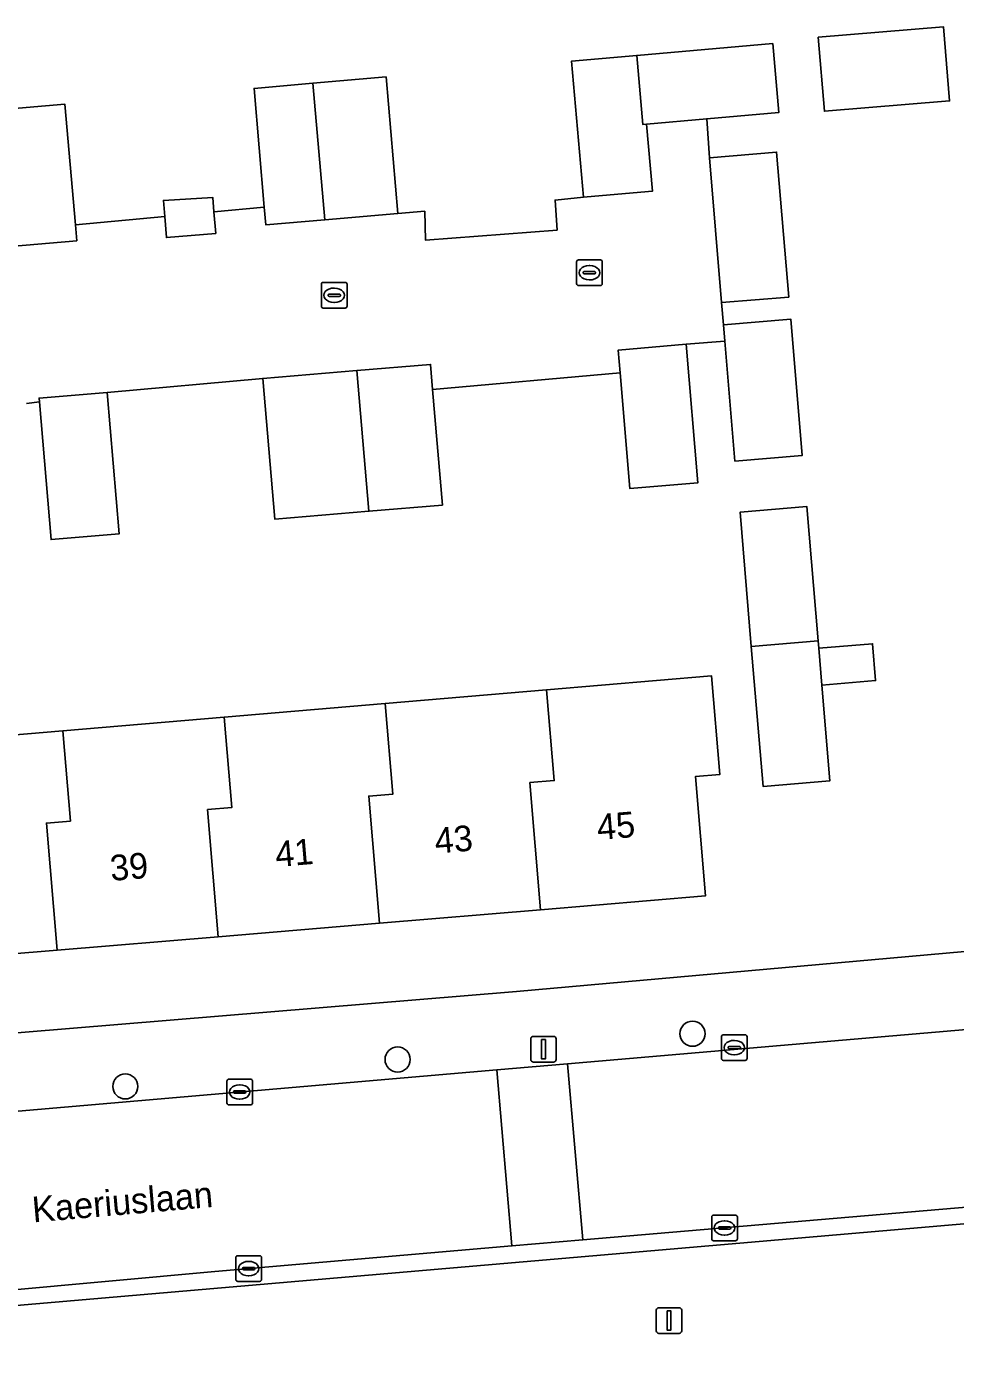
# Model space of a CAD drawing. Extents: x 162989 to 165008, y 383432 to 384338.
# Drawn here: x 164102.5 to 164138.7, y 383759.5 to 383811.7 of the extents above; entities that cross this region are included whole.
import ezdxf

# ---------------------------------------------------------------- set-up
doc = ezdxf.new("R2010")
doc.units = 0
for name, color, linetype in [('IMGEO_Boom', 7, 'Continuous'), ('IMGEO_Erf', 7, 'Continuous'), ('IMGEO_Groenvoorziening', 7, 'Continuous'), ('IMGEO_Kolk', 7, 'Continuous'), ('IMGEO_Lichtmast', 7, 'Continuous'), ('IMGEO_Openbare_ruimte_label', 7, 'Continuous'), ('IMGEO_Pand', 7, 'Continuous'), ('IMGEO_Pand_nummerreeks', 7, 'Continuous'), ('IMGEO_Rijbaan_lokaal_open', 7, 'Continuous'), ('IMGEO_Verkeersbordpaal', 7, 'Continuous'), ('IMGEO_Voetpad_open', 7, 'Continuous')]:
    doc.layers.add(name, color=color, linetype=linetype)

msp = doc.modelspace()

# ---------------------------------------------------------------- linework, layer by layer
at = {"layer": 'IMGEO_Boom'}
for centre in [(164128.474, 383772.403), (164116.984, 383771.397), (164106.376, 383770.348)]:
    msp.add_circle(centre, 0.489, dxfattribs=at)
at = {"layer": 'IMGEO_Erf'}
for points in [[(164133.371, 383811.252), (164138.248, 383811.657), (164138.488, 383808.766), (164133.611, 383808.362)], [(164132.932, 383792.952), (164133.371, 383787.723), (164133.395, 383787.431), (164135.485, 383787.606), (164135.606, 383786.169), (164133.516, 383785.993), (164133.829, 383782.263), (164131.22, 383782.044), (164130.762, 383787.504), (164130.323, 383792.733)]]:
    msp.add_lwpolyline(points, close=True, dxfattribs=at)
for points in [[(164101.449, 383808.414), (164104.025, 383808.637), (164104.431, 383803.941), (164107.91, 383804.265), (164107.859, 383804.884), (164109.782, 383805.002), (164109.829, 383804.443), (164111.79, 383804.626), (164111.39, 383809.255), (164113.684, 383809.453), (164116.536, 383809.7), (164116.996, 383804.383), (164118.039, 383804.467), (164118.076, 383803.337), (164123.199, 383803.732), (164123.122, 383804.902), (164124.223, 383805.01), (164123.763, 383810.32), (164126.303, 383810.54), (164131.6, 383810.998), (164131.832, 383808.311), (164129.028, 383808.068), (164129.132, 383806.552), (164131.75, 383806.772), (164132.224, 383801.122), (164129.606, 383800.903), (164129.679, 383800.038), (164132.303, 383800.258), (164132.748, 383794.945), (164130.125, 383794.725), (164129.733, 383799.4), (164128.221, 383799.277), (164128.676, 383793.877), (164126.034, 383793.655), (164125.654, 383798.168)], [(164125.654, 383798.168), (164118.349, 383797.52), (164118.729, 383793.012), (164115.866, 383792.771), (164112.195, 383792.462), (164111.733, 383797.946), (164105.672, 383797.403), (164106.136, 383791.887), (164103.483, 383791.664), (164103.031, 383797.037), (164102.526, 383796.966)], [(164097.659, 383783.675), (164103.94, 383784.208), (164110.222, 383784.74), (164116.502, 383785.281), (164122.785, 383785.81), (164129.216, 383786.352), (164129.539, 383782.513), (164128.593, 383782.433), (164128.985, 383777.779), (164122.556, 383777.237), (164116.277, 383776.708), (164109.997, 383776.179), (164103.716, 383775.662), (164097.436, 383775.136)], [(164086.93, 383771.177), (164121.61, 383774.053), (164152.912, 383776.838)]]:
    msp.add_lwpolyline(points, dxfattribs=at)
at = {"layer": 'IMGEO_Groenvoorziening'}
msp.add_lwpolyline([(164144.916, 383765.499), (164133.333, 383764.5), (164096.403, 383761.317), (164094.919, 383761.189), (164080.016, 383759.904), (164147.725, 383723.47), (164150.071, 383727.942), (164134.867, 383736.085), (164147.454, 383759.501)], dxfattribs=at)
at = {"layer": 'IMGEO_Kolk'}
for p, q in [((164123.956, 383801.642), (164123.956, 383802.494)), ((164124.031, 383802.568), (164124.883, 383802.568)), ((164124.444, 383802.348), (164124.469, 383802.348)), ((164124.957, 383802.494), (164124.957, 383801.642)), ((164124.215, 383802.062), (164124.215, 383802.074)), ((164124.653, 383802.025), (164124.255, 383802.025)), ((164124.258, 383802.111), (164124.656, 383802.111)), ((164124.467, 383801.788), (164124.442, 383801.788)), ((164124.699, 383802.074), (164124.699, 383802.062)), ((164114.015, 383800.764), (164114.015, 383801.616)), ((164114.09, 383801.69), (164114.942, 383801.69)), ((164114.274, 383801.184), (164114.274, 383801.196)), ((164114.317, 383801.233), (164114.715, 383801.233)), ((164114.503, 383801.47), (164114.528, 383801.47)), ((164114.758, 383801.196), (164114.758, 383801.184)), ((164115.016, 383801.616), (164115.016, 383800.764)), ((164124.883, 383801.568), (164124.031, 383801.568)), ((164114.942, 383800.69), (164114.09, 383800.69)), ((164114.712, 383801.147), (164114.314, 383801.147)), ((164114.526, 383800.91), (164114.501, 383800.91)), ((164129.6, 383771.436), (164129.6, 383772.288)), ((164129.675, 383772.362), (164130.527, 383772.362)), ((164130.088, 383772.142), (164130.113, 383772.142)), ((164130.601, 383772.288), (164130.601, 383771.436)), ((164129.859, 383771.856), (164129.859, 383771.868)), ((164130.297, 383771.819), (164129.899, 383771.819)), ((164129.902, 383771.905), (164130.3, 383771.905)), ((164130.111, 383771.582), (164130.086, 383771.582)), ((164130.343, 383771.868), (164130.343, 383771.856)), ((164130.527, 383771.362), (164129.675, 383771.362)), ((164110.331, 383769.705), (164110.331, 383770.557)), ((164110.406, 383770.631), (164111.258, 383770.631)), ((164111.332, 383770.557), (164111.332, 383769.705)), ((164110.59, 383770.125), (164110.59, 383770.137)), ((164111.028, 383770.088), (164110.63, 383770.088)), ((164110.633, 383770.174), (164111.031, 383770.174)), ((164110.819, 383770.411), (164110.844, 383770.411)), ((164111.074, 383770.137), (164111.074, 383770.125)), ((164111.258, 383769.631), (164110.406, 383769.631)), ((164110.842, 383769.851), (164110.817, 383769.851)), ((164129.222, 383764.406), (164129.222, 383765.258)), ((164129.297, 383765.332), (164130.149, 383765.332)), ((164130.223, 383765.258), (164130.223, 383764.406)), ((164129.481, 383764.826), (164129.481, 383764.838)), ((164129.919, 383764.789), (164129.521, 383764.789)), ((164129.524, 383764.875), (164129.922, 383764.875)), ((164129.71, 383765.112), (164129.735, 383765.112)), ((164129.965, 383764.838), (164129.965, 383764.826)), ((164130.149, 383764.332), (164129.297, 383764.332)), ((164129.733, 383764.552), (164129.708, 383764.552)), ((164110.681, 383762.822), (164110.681, 383763.674)), ((164110.756, 383763.748), (164111.608, 383763.748)), ((164111.682, 383763.674), (164111.682, 383762.822)), ((164110.94, 383763.242), (164110.94, 383763.254)), ((164111.378, 383763.205), (164110.98, 383763.205)), ((164110.983, 383763.291), (164111.381, 383763.291)), ((164111.169, 383763.528), (164111.194, 383763.528)), ((164111.424, 383763.254), (164111.424, 383763.242)), ((164111.608, 383762.748), (164110.756, 383762.748)), ((164111.192, 383762.968), (164111.167, 383762.968))]:
    msp.add_line(p, q, dxfattribs=at)
for points in [[(164123.956, 383801.642), (164123.956, 383802.494)], [(164124.031, 383802.568), (164124.883, 383802.568)], [(164124.957, 383802.494), (164124.957, 383801.642)], [(164114.015, 383800.764), (164114.015, 383801.616)], [(164114.09, 383801.69), (164114.942, 383801.69)], [(164115.016, 383801.616), (164115.016, 383800.764)], [(164124.883, 383801.568), (164124.031, 383801.568)], [(164114.942, 383800.69), (164114.09, 383800.69)], [(164129.6, 383771.436), (164129.6, 383772.288)], [(164129.675, 383772.362), (164130.527, 383772.362)], [(164130.601, 383772.288), (164130.601, 383771.436)], [(164130.527, 383771.362), (164129.675, 383771.362)], [(164110.331, 383769.705), (164110.331, 383770.557)], [(164110.406, 383770.631), (164111.258, 383770.631)], [(164111.332, 383770.557), (164111.332, 383769.705)], [(164111.258, 383769.631), (164110.406, 383769.631)], [(164129.222, 383764.406), (164129.222, 383765.258)], [(164129.297, 383765.332), (164130.149, 383765.332)], [(164130.223, 383765.258), (164130.223, 383764.406)], [(164130.149, 383764.332), (164129.297, 383764.332)], [(164110.681, 383762.822), (164110.681, 383763.674)], [(164110.756, 383763.748), (164111.608, 383763.748)], [(164111.682, 383763.674), (164111.682, 383762.822)], [(164111.608, 383762.748), (164110.756, 383762.748)]]:
    msp.add_lwpolyline(points, dxfattribs=at)
for centre, radius, start, end in [((164124.033, 383802.492), 0.0765, 91.552, 178.448), ((164124.033, 383802.492), 0.0765, 91.552, 178.448), ((164124.881, 383802.492), 0.0765, 1.552, 88.448), ((164124.881, 383802.492), 0.0765, 1.552, 88.448), ((164124.255, 383802.071), 0.0403, 85.8775, 175.7526), ((164124.252, 383802.061), 0.0366, 178.938, 274.7102), ((164124.656, 383802.068), 0.043, 264.8664, 352.4533), ((164124.66, 383802.073), 0.0386, 1.7309, 96.639), ((164114.092, 383801.614), 0.0765, 91.552, 178.448), ((164114.092, 383801.614), 0.0765, 91.552, 178.448), ((164114.314, 383801.193), 0.0403, 85.8775, 175.7526), ((164114.719, 383801.195), 0.0386, 1.7309, 96.639), ((164114.94, 383801.614), 0.0765, 1.552, 88.448), ((164114.94, 383801.614), 0.0765, 1.552, 88.448), ((164124.033, 383801.644), 0.0765, 181.552, 268.448), ((164124.033, 383801.644), 0.0765, 181.552, 268.448), ((164124.881, 383801.644), 0.0765, 271.552, 358.448), ((164124.881, 383801.644), 0.0765, 271.552, 358.448), ((164114.092, 383800.766), 0.0765, 181.552, 268.448), ((164114.092, 383800.766), 0.0765, 181.552, 268.448), ((164114.311, 383801.183), 0.0366, 178.938, 274.7102), ((164114.715, 383801.19), 0.043, 264.8664, 352.4533), ((164114.94, 383800.766), 0.0765, 271.552, 358.448), ((164114.94, 383800.766), 0.0765, 271.552, 358.448), ((164129.677, 383772.286), 0.0765, 91.552, 178.448), ((164129.677, 383772.286), 0.0765, 91.552, 178.448), ((164130.525, 383772.286), 0.0765, 1.552, 88.448), ((164130.525, 383772.286), 0.0765, 1.552, 88.448), ((164129.899, 383771.865), 0.0403, 85.8775, 175.7526), ((164129.896, 383771.855), 0.0366, 178.938, 274.7102), ((164130.3, 383771.862), 0.043, 264.8664, 352.4533), ((164130.304, 383771.867), 0.0386, 1.7309, 96.639), ((164129.677, 383771.438), 0.0765, 181.552, 268.448), ((164129.677, 383771.438), 0.0765, 181.552, 268.448), ((164130.525, 383771.438), 0.0765, 271.552, 358.448), ((164130.525, 383771.438), 0.0765, 271.552, 358.448), ((164110.408, 383770.555), 0.0765, 91.552, 178.448), ((164110.408, 383770.555), 0.0765, 91.552, 178.448), ((164111.256, 383770.555), 0.0765, 1.552, 88.448), ((164111.256, 383770.555), 0.0765, 1.552, 88.448), ((164110.63, 383770.134), 0.0403, 85.8775, 175.7526), ((164110.627, 383770.124), 0.0366, 178.938, 274.7102), ((164111.031, 383770.131), 0.043, 264.8664, 352.4533), ((164111.035, 383770.136), 0.0386, 1.7309, 96.639), ((164110.408, 383769.707), 0.0765, 181.552, 268.448), ((164110.408, 383769.707), 0.0765, 181.552, 268.448), ((164111.256, 383769.707), 0.0765, 271.552, 358.448), ((164111.256, 383769.707), 0.0765, 271.552, 358.448), ((164129.299, 383765.256), 0.0765, 91.552, 178.448), ((164129.299, 383765.256), 0.0765, 91.552, 178.448), ((164130.147, 383765.256), 0.0765, 1.552, 88.448), ((164130.147, 383765.256), 0.0765, 1.552, 88.448), ((164129.521, 383764.835), 0.0403, 85.8775, 175.7526), ((164129.518, 383764.825), 0.0366, 178.938, 274.7102), ((164129.922, 383764.832), 0.043, 264.8664, 352.4533), ((164129.926, 383764.837), 0.0386, 1.7309, 96.639), ((164129.299, 383764.408), 0.0765, 181.552, 268.448), ((164129.299, 383764.408), 0.0765, 181.552, 268.448), ((164130.147, 383764.408), 0.0765, 271.552, 358.448), ((164130.147, 383764.408), 0.0765, 271.552, 358.448), ((164110.758, 383763.672), 0.0765, 91.552, 178.448), ((164110.758, 383763.672), 0.0765, 91.552, 178.448), ((164111.606, 383763.672), 0.0765, 1.552, 88.448), ((164111.606, 383763.672), 0.0765, 1.552, 88.448), ((164110.98, 383763.251), 0.0403, 85.8775, 175.7526), ((164110.977, 383763.241), 0.0366, 178.938, 274.7102), ((164111.381, 383763.248), 0.043, 264.8664, 352.4533), ((164111.385, 383763.253), 0.0386, 1.7309, 96.639), ((164110.758, 383762.824), 0.0765, 181.552, 268.448), ((164110.758, 383762.824), 0.0765, 181.552, 268.448), ((164111.606, 383762.824), 0.0765, 271.552, 358.448), ((164111.606, 383762.824), 0.0765, 271.552, 358.448)]:
    msp.add_arc(centre, radius, start, end, dxfattribs=at)
for centre, major_axis, ratio, start_param, end_param in [((164124.443, 383802.068), (-0.387, 0.002), 0.722429, 4.712389, 7.853982), ((164124.468, 383802.068), (-0.39, 0.002), 0.717154, 1.570796, 4.712389), ((164114.502, 383801.19), (-0.387, 0.002), 0.722429, 4.712389, 7.853982), ((164114.527, 383801.19), (-0.39, 0.002), 0.717154, 1.570796, 4.712389), ((164130.087, 383771.862), (-0.387, 0.002), 0.722429, 4.712389, 7.853982), ((164130.112, 383771.862), (-0.39, 0.002), 0.717154, 1.570796, 4.712389), ((164110.818, 383770.131), (-0.387, 0.002), 0.722429, 4.712389, 7.853982), ((164110.843, 383770.131), (-0.39, 0.002), 0.717154, 1.570796, 4.712389), ((164129.709, 383764.832), (-0.387, 0.002), 0.722429, 4.712389, 7.853982), ((164129.734, 383764.832), (-0.39, 0.002), 0.717154, 1.570796, 4.712389), ((164111.168, 383763.248), (-0.387, 0.002), 0.722429, 4.712389, 7.853982), ((164111.193, 383763.248), (-0.39, 0.002), 0.717154, 1.570796, 4.712389)]:
    msp.add_ellipse(centre, major_axis=major_axis, ratio=ratio, start_param=start_param, end_param=end_param, dxfattribs=at)
at = {"layer": 'IMGEO_Lichtmast'}
for p, q in [((164122.172, 383771.398), (164122.172, 383772.198)), ((164122.172, 383772.198), (164122.172, 383771.398)), ((164122.272, 383772.298), (164123.062, 383772.298)), ((164123.062, 383772.298), (164122.272, 383772.298)), ((164123.162, 383772.198), (164123.162, 383771.398)), ((164123.162, 383771.398), (164123.162, 383772.198)), ((164123.062, 383771.298), (164122.272, 383771.298)), ((164122.272, 383771.298), (164123.062, 383771.298))]:
    msp.add_line(p, q, dxfattribs=at)
msp.add_lwpolyline([(164122.592, 383772.173), (164122.742, 383772.173), (164122.742, 383771.423), (164122.592, 383771.423), (164122.592, 383772.173)], dxfattribs=at)
for centre, start, end in [((164122.272, 383772.198), 90, 180), ((164122.272, 383772.198), 90, 180), ((164123.062, 383772.198), 0, 90), ((164123.062, 383772.198), 360, 90), ((164122.272, 383771.398), 180, 270), ((164122.272, 383771.398), 180, 270), ((164123.062, 383771.398), 270, 0), ((164123.062, 383771.398), 270, 0)]:
    msp.add_arc(centre, 0.1, start, end, dxfattribs=at)
at = {"layer": 'IMGEO_Pand'}
for points in [[(164133.371, 383811.252), (164133.611, 383808.362), (164138.488, 383808.766), (164138.248, 383811.657)], [(164131.6, 383810.998), (164126.303, 383810.54), (164126.536, 383807.852), (164126.682, 383807.865), (164129.028, 383808.068), (164131.832, 383808.311)], [(164126.682, 383807.865), (164126.536, 383807.852), (164126.303, 383810.54), (164123.763, 383810.32), (164124.223, 383805.01), (164126.763, 383805.23), (164126.909, 383805.243)], [(164114.144, 383804.136), (164116.996, 383804.383), (164116.536, 383809.7), (164113.684, 383809.453)], [(164114.144, 383804.136), (164113.684, 383809.453), (164111.39, 383809.255), (164111.79, 383804.626), (164111.85, 383803.938)], [(164101.449, 383808.414), (164101.493, 383807.9), (164101.909, 383803.094), (164104.485, 383803.316), (164104.431, 383803.941), (164104.025, 383808.637)], [(164129.606, 383800.903), (164132.224, 383801.122), (164131.75, 383806.772), (164129.132, 383806.552)], [(164109.829, 383804.443), (164109.782, 383805.002), (164107.859, 383804.884), (164107.91, 383804.265), (164107.979, 383803.441), (164109.899, 383803.6)], [(164129.733, 383799.4), (164130.125, 383794.725), (164132.748, 383794.945), (164132.303, 383800.258), (164129.679, 383800.038)], [(164125.654, 383798.168), (164126.034, 383793.655), (164128.676, 383793.877), (164128.221, 383799.277), (164125.579, 383799.055)], [(164115.401, 383798.255), (164111.733, 383797.946), (164112.195, 383792.462), (164115.866, 383792.771)], [(164115.401, 383798.255), (164115.866, 383792.771), (164118.729, 383793.012), (164118.349, 383797.52), (164118.267, 383798.497)], [(164105.672, 383797.403), (164103.019, 383797.18), (164103.031, 383797.037), (164103.483, 383791.664), (164106.136, 383791.887)], [(164130.762, 383787.504), (164133.371, 383787.723), (164132.932, 383792.952), (164130.323, 383792.733)], [(164133.516, 383785.993), (164133.395, 383787.431), (164133.371, 383787.723), (164130.762, 383787.504), (164131.22, 383782.044), (164133.829, 383782.263)], [(164133.395, 383787.431), (164133.516, 383785.993), (164135.606, 383786.169), (164135.485, 383787.606)], [(164122.556, 383777.237), (164128.985, 383777.779), (164128.593, 383782.433), (164129.539, 383782.513), (164129.216, 383786.352), (164122.785, 383785.81), (164123.084, 383782.273), (164122.141, 383782.194)], [(164116.277, 383776.708), (164122.556, 383777.237), (164122.141, 383782.194), (164123.084, 383782.273), (164122.785, 383785.81), (164116.502, 383785.281), (164116.802, 383781.746), (164115.861, 383781.667)], [(164116.277, 383776.708), (164115.861, 383781.667), (164116.802, 383781.746), (164116.502, 383785.281), (164110.222, 383784.74), (164110.52, 383781.219), (164109.581, 383781.14), (164109.997, 383776.179)], [(164109.997, 383776.179), (164109.581, 383781.14), (164110.52, 383781.219), (164110.222, 383784.74), (164103.94, 383784.208), (164104.238, 383780.692), (164103.301, 383780.614), (164103.716, 383775.662)], [(164097.659, 383783.675), (164097.956, 383780.166), (164097.021, 383780.088), (164097.436, 383775.136), (164103.716, 383775.662), (164103.301, 383780.614), (164104.238, 383780.692), (164103.94, 383784.208)]]:
    msp.add_lwpolyline(points, close=True, dxfattribs=at)
at = {"layer": 'IMGEO_Rijbaan_lokaal_open'}
for points in [[(164102.526, 383796.966), (164103.031, 383797.037), (164103.019, 383797.18), (164105.672, 383797.403), (164111.733, 383797.946), (164115.401, 383798.255), (164118.267, 383798.497), (164118.349, 383797.52), (164125.654, 383798.168), (164125.579, 383799.055), (164128.221, 383799.277), (164129.733, 383799.4), (164129.679, 383800.038), (164129.606, 383800.903), (164129.132, 383806.552), (164129.028, 383808.068), (164126.682, 383807.865), (164126.909, 383805.243), (164126.763, 383805.23), (164124.223, 383805.01), (164123.122, 383804.902), (164123.199, 383803.732), (164118.076, 383803.337), (164118.039, 383804.467), (164116.996, 383804.383), (164114.144, 383804.136), (164111.85, 383803.938), (164111.79, 383804.626), (164109.829, 383804.443), (164109.899, 383803.6), (164107.979, 383803.441), (164107.91, 383804.265), (164104.431, 383803.941), (164104.485, 383803.316), (164101.909, 383803.094)], [(164167.819, 383767.897), (164160.568, 383771.973), (164150.608, 383773.554), (164123.606, 383771.227), (164124.198, 383764.365), (164145.077, 383766.154)], [(164080.8, 383760.478), (164109.867, 383763.137), (164121.439, 383764.129), (164120.847, 383770.989), (164086.099, 383767.995), (164081.202, 383767.573), (164080.172, 383767.484)]]:
    msp.add_lwpolyline(points, dxfattribs=at)
msp.add_lwpolyline([(164120.847, 383770.989), (164121.439, 383764.129), (164124.198, 383764.365), (164123.606, 383771.227)], close=True, dxfattribs=at)
at = {"layer": 'IMGEO_Verkeersbordpaal'}
for p, q in [((164127.061, 383760.822), (164127.061, 383761.622)), ((164127.061, 383761.622), (164127.061, 383760.822)), ((164127.161, 383761.722), (164127.951, 383761.722)), ((164127.951, 383761.722), (164127.161, 383761.722)), ((164128.051, 383761.622), (164128.051, 383760.822)), ((164128.051, 383760.822), (164128.051, 383761.622)), ((164127.951, 383760.722), (164127.161, 383760.722)), ((164127.161, 383760.722), (164127.951, 383760.722))]:
    msp.add_line(p, q, dxfattribs=at)
msp.add_lwpolyline([(164127.481, 383761.597), (164127.631, 383761.597), (164127.631, 383760.847), (164127.481, 383760.847), (164127.481, 383761.597)], dxfattribs=at)
for centre, start, end in [((164127.161, 383761.622), 90, 180), ((164127.161, 383761.622), 90, 180), ((164127.951, 383761.622), 0, 90), ((164127.951, 383761.622), 360, 90), ((164127.161, 383760.822), 180, 270), ((164127.161, 383760.822), 180, 270), ((164127.951, 383760.822), 270, 0), ((164127.951, 383760.822), 270, 0)]:
    msp.add_arc(centre, 0.1, start, end, dxfattribs=at)
at = {"layer": 'IMGEO_Voetpad_open'}
for points in [[(164152.912, 383776.838), (164121.61, 383774.053), (164086.93, 383771.177), (164079.558, 383770.469), (164079.021, 383770.417)], [(164080.172, 383767.484), (164081.202, 383767.573), (164081.161, 383768.07), (164086.058, 383768.487), (164086.099, 383767.995), (164120.847, 383770.989), (164123.606, 383771.227), (164150.608, 383773.554)], [(164145.077, 383766.154), (164124.198, 383764.365), (164121.439, 383764.129), (164109.867, 383763.137), (164080.8, 383760.478)], [(164094.919, 383761.189), (164096.403, 383761.317), (164133.333, 383764.5), (164144.916, 383765.499)]]:
    msp.add_lwpolyline(points, dxfattribs=at)

# ---------------------------------------------------------------- texts
at = {"layer": 'IMGEO_Openbare_ruimte_label'}
msp.add_text('Kaeriuslaan', height=1, rotation=4.935, dxfattribs=at).set_placement((164102.787, 383765.045))
at = {"layer": 'IMGEO_Pand_nummerreeks'}
for s, p in [('45', (164124.788, 383779.954)), ('43', (164118.466, 383779.422)), ('41', (164112.257, 383778.899)), ('39', (164105.822, 383778.357))]:
    msp.add_text(s, height=1, rotation=4.8151, dxfattribs=at).set_placement(p)

doc.saveas('drawing.dxf')
